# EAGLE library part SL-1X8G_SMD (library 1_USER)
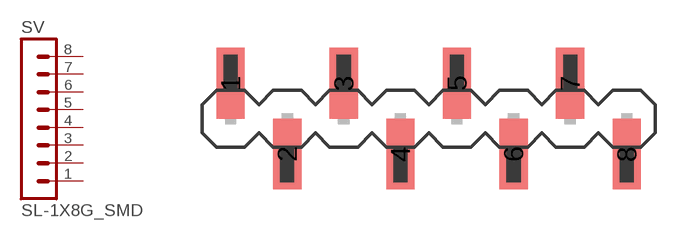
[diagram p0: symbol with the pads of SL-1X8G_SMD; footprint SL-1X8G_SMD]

Designator prefix SV

## SL-1X8G_SMD  [SL-1X8G_SMD]
1  1  pas
2  2  pas
3  3  pas
4  4  pas
5  5  pas
6  6  pas
7  7  pas
8  8  pas

## Footprint SL-1X8G_SMD (pad centres in mm)
smd 1.27 x 3.17: 1 -8.89,1.587; 2 -6.35,-1.587; 3 -3.81,1.587; 4 -1.27,-1.587; 5 1.27,1.587; 6 3.81,-1.587; 7 6.35,1.587; 8 8.89,-1.587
